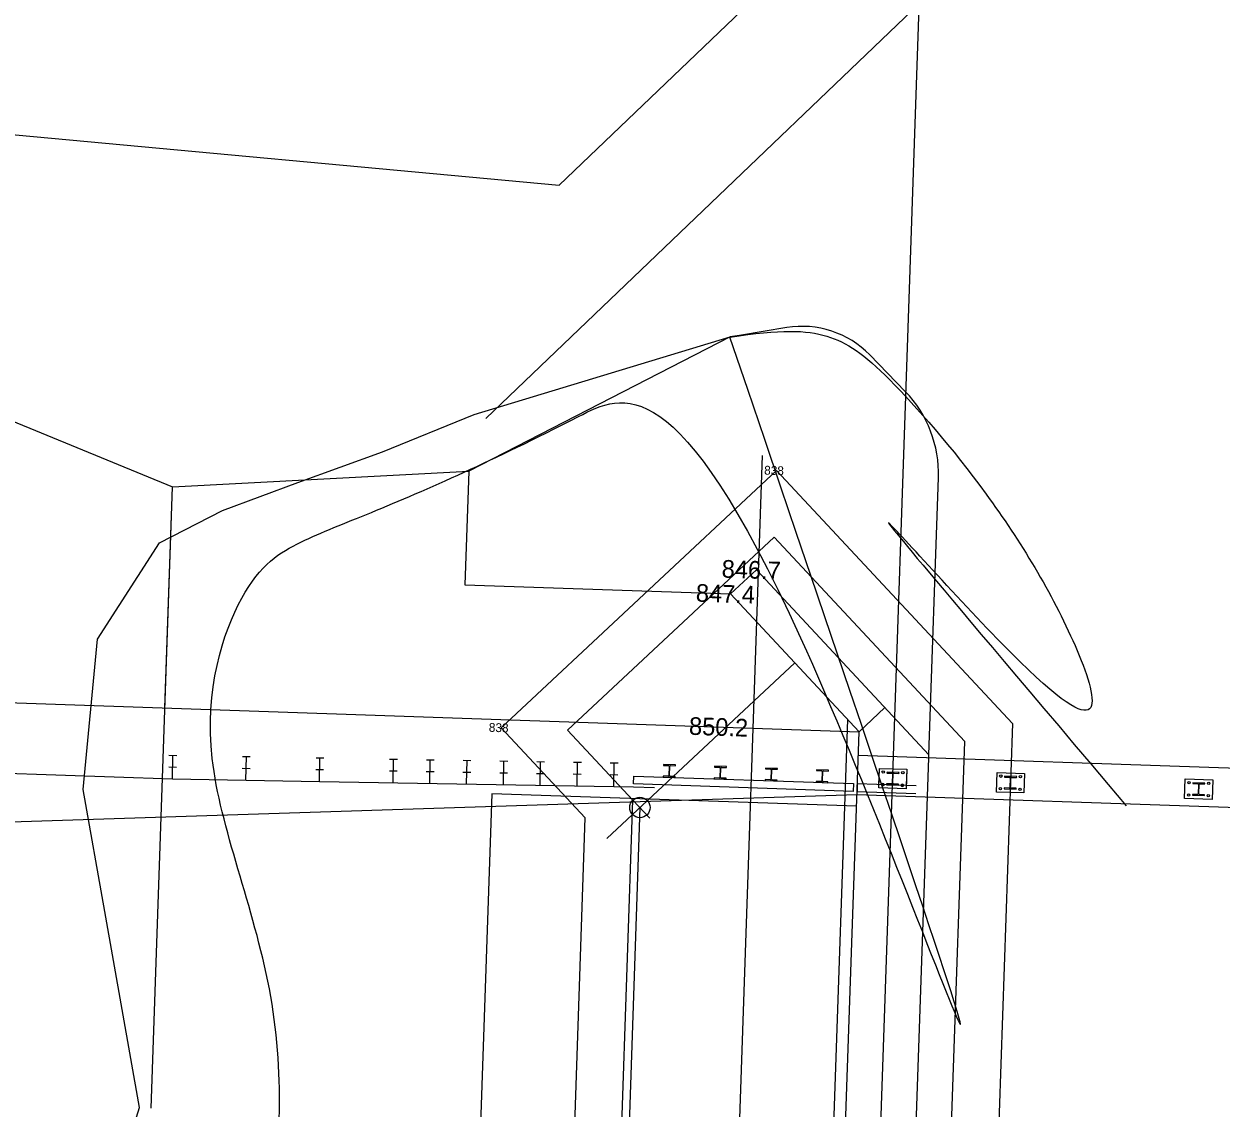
# Model space of a CAD drawing. Extents: x 2191309 to 2193046, y 863659 to 865133.
# Drawn here: x 2192617.6 to 2192668.4, y 863931.1 to 863977.1 of the extents above; entities that cross this region are included whole.
import ezdxf

# ---------------------------------------------------------------- set-up
doc = ezdxf.new("R2010")
doc.units = 0
for name, color, linetype in [('D_Bridge_Abutment', 7, 'Continuous'), ('D_Bridge_Deck', 7, 'Continuous'), ('D_Bridge_Railing', 7, 'Continuous'), ('D_Bridge_Substructure_Hidden', 7, 'Continuous'), ('D_Guardrail_Beam_Lt', 7, 'Continuous'), ('D_Roadway_Edge_Shoulder', 7, 'Continuous'), ('D_Roadway_Edge_TW', 7, 'Continuous'), ('D_Slope_ClearingLimitLine', 7, 'Continuous'), ('D_Slope_Direction', 7, 'Continuous'), ('D_Slope_Toe', 7, 'Continuous'), ('DIMENSIONS', 7, 'Continuous'), ('JUNK', 7, 'Continuous')]:
    doc.layers.add(name, color=color, linetype=linetype)

msp = doc.modelspace()

# ---------------------------------------------------------------- linework, layer by layer
at = {"layer": 'D_Bridge_Abutment'}
for p, q in [((2192649.968, 863964.217), (2192647.951, 863963.884)), ((2192654.997, 863961.503), (2192653.49, 863963.056)), ((2192656.002, 863946.079), (2192656.406, 863957.849)), ((2192647.575, 863952.908), (2192648.671, 863953.932)), ((2192647.575, 863952.908), (2192648.671, 863953.932)), ((2192656.002, 863946.079), (2192648.671, 863953.932)), ((2192648.671, 863953.932), (2192656.002, 863946.079)), ((2192653.034, 863947.06), (2192647.575, 863952.908)), ((2192653.034, 863947.06), (2192654.131, 863948.084)), ((2192651.868, 863913.08), (2192653.034, 863947.06)), ((2192655.998, 863945.958), (2192656.002, 863946.079))]:
    msp.add_line(p, q, dxfattribs=at)
msp.add_lwpolyline([(2192647.951, 863963.884), (2192647.562, 863963.82), (2192636.456, 863958.126), (2192636.29, 863953.295), (2192647.575, 863952.908)], dxfattribs=at)
for centre, radius, start, end in [((2192650.619, 863960.27), 4, 44.1436, 99.3716), ((2192651.409, 863958.021), 5, 358.0343, 44.1436)]:
    msp.add_arc(centre, radius, start, end, dxfattribs=at)
at = {"layer": 'D_Bridge_Deck'}
for p, q in [((2192653, 863946.061), (2192689.978, 863944.792)), ((2192652.943, 863944.395), (2192689.921, 863943.126))]:
    msp.add_line(p, q, dxfattribs=at)
at = {"layer": 'D_Bridge_Railing'}
for p, q in [((2192644.728, 863945.668), (2192644.727, 863945.63)), ((2192644.727, 863945.63), (2192644.937, 863945.622)), ((2192645.234, 863945.65), (2192644.728, 863945.668)), ((2192644.966, 863945.592), (2192644.952, 863945.196)), ((2192644.979, 863945.195), (2192644.992, 863945.591)), ((2192645.023, 863945.62), (2192645.233, 863945.612)), ((2192645.233, 863945.612), (2192645.234, 863945.65)), ((2192646.893, 863945.593), (2192646.892, 863945.555)), ((2192647.4, 863945.576), (2192646.893, 863945.593)), ((2192647.399, 863945.538), (2192647.4, 863945.576)), ((2192644.711, 863945.174), (2192644.71, 863945.136)), ((2192644.71, 863945.136), (2192645.216, 863945.119)), ((2192644.921, 863945.167), (2192644.711, 863945.174)), ((2192645.218, 863945.157), (2192645.007, 863945.164)), ((2192645.216, 863945.119), (2192645.218, 863945.157)), ((2192646.877, 863945.1), (2192646.875, 863945.062)), ((2192646.875, 863945.062), (2192647.382, 863945.045)), ((2192647.087, 863945.093), (2192646.877, 863945.1)), ((2192646.892, 863945.555), (2192647.102, 863945.548)), ((2192647.131, 863945.517), (2192647.117, 863945.121)), ((2192647.144, 863945.12), (2192647.158, 863945.516)), ((2192647.383, 863945.082), (2192647.173, 863945.09)), ((2192647.188, 863945.545), (2192647.399, 863945.538)), ((2192647.382, 863945.045), (2192647.383, 863945.082)), ((2192649.059, 863945.519), (2192649.058, 863945.481)), ((2192649.058, 863945.481), (2192649.268, 863945.474)), ((2192649.565, 863945.502), (2192649.059, 863945.519)), ((2192649.296, 863945.443), (2192649.283, 863945.047)), ((2192649.309, 863945.046), (2192649.323, 863945.442)), ((2192649.354, 863945.471), (2192649.564, 863945.464)), ((2192649.564, 863945.464), (2192649.565, 863945.502)), ((2192651.224, 863945.445), (2192651.223, 863945.407)), ((2192651.223, 863945.407), (2192651.433, 863945.4)), ((2192651.731, 863945.427), (2192651.224, 863945.445)), ((2192651.462, 863945.369), (2192651.448, 863944.973)), ((2192651.475, 863944.972), (2192651.488, 863945.368)), ((2192651.519, 863945.397), (2192651.729, 863945.389)), ((2192651.729, 863945.389), (2192651.731, 863945.427)), ((2192654.221, 863945.341), (2192654.219, 863945.305)), ((2192654.219, 863945.305), (2192654.431, 863945.298)), ((2192654.223, 863945.342), (2192654.221, 863945.304)), ((2192654.731, 863945.324), (2192654.221, 863945.341)), ((2192654.221, 863945.304), (2192654.431, 863945.297)), ((2192654.729, 863945.324), (2192654.223, 863945.342)), ((2192654.46, 863945.266), (2192654.446, 863944.87)), ((2192654.46, 863945.266), (2192654.447, 863944.869)), ((2192654.473, 863944.869), (2192654.487, 863945.265)), ((2192654.473, 863944.869), (2192654.486, 863945.265)), ((2192654.517, 863945.294), (2192654.728, 863945.286)), ((2192654.518, 863945.295), (2192654.729, 863945.287)), ((2192654.728, 863945.286), (2192654.729, 863945.324)), ((2192654.729, 863945.287), (2192654.731, 863945.324)), ((2192659.218, 863945.17), (2192659.216, 863945.133)), ((2192659.216, 863945.133), (2192659.428, 863945.126)), ((2192659.728, 863945.152), (2192659.218, 863945.17)), ((2192659.457, 863945.094), (2192659.444, 863944.698)), ((2192659.47, 863944.697), (2192659.483, 863945.093)), ((2192659.515, 863945.123), (2192659.727, 863945.116)), ((2192659.727, 863945.116), (2192659.728, 863945.152)), ((2192649.042, 863945.026), (2192649.041, 863944.988)), ((2192649.041, 863944.988), (2192649.547, 863944.97)), ((2192649.252, 863945.018), (2192649.042, 863945.026)), ((2192649.548, 863945.008), (2192649.338, 863945.015)), ((2192649.547, 863944.97), (2192649.548, 863945.008)), ((2192651.207, 863944.951), (2192651.206, 863944.913)), ((2192651.206, 863944.913), (2192651.712, 863944.896)), ((2192651.417, 863944.944), (2192651.207, 863944.951)), ((2192651.714, 863944.934), (2192651.504, 863944.941)), ((2192651.712, 863944.896), (2192651.714, 863944.934)), ((2192654.204, 863944.847), (2192654.202, 863944.81)), ((2192654.202, 863944.81), (2192654.713, 863944.793)), ((2192654.206, 863944.848), (2192654.204, 863944.81)), ((2192654.415, 863944.84), (2192654.204, 863944.847)), ((2192654.204, 863944.81), (2192654.711, 863944.793)), ((2192654.416, 863944.841), (2192654.206, 863944.848)), ((2192654.712, 863944.831), (2192654.502, 863944.838)), ((2192654.714, 863944.829), (2192654.503, 863944.837)), ((2192654.711, 863944.793), (2192654.712, 863944.831)), ((2192654.713, 863944.793), (2192654.714, 863944.829)), ((2192659.201, 863944.675), (2192659.199, 863944.639)), ((2192659.199, 863944.639), (2192659.71, 863944.621)), ((2192659.412, 863944.668), (2192659.201, 863944.675)), ((2192659.711, 863944.658), (2192659.5, 863944.665)), ((2192659.71, 863944.621), (2192659.711, 863944.658)), ((2192667.213, 863944.895), (2192667.212, 863944.859)), ((2192667.212, 863944.859), (2192667.423, 863944.852)), ((2192667.723, 863944.878), (2192667.213, 863944.895)), ((2192667.453, 863944.82), (2192667.439, 863944.423)), ((2192667.465, 863944.423), (2192667.479, 863944.819)), ((2192667.511, 863944.849), (2192667.722, 863944.842)), ((2192667.722, 863944.842), (2192667.723, 863944.878)), ((2192667.196, 863944.401), (2192667.195, 863944.365)), ((2192667.195, 863944.365), (2192667.705, 863944.347)), ((2192667.407, 863944.394), (2192667.196, 863944.401)), ((2192667.706, 863944.383), (2192667.495, 863944.391)), ((2192667.705, 863944.347), (2192667.706, 863944.383))]:
    msp.add_line(p, q, dxfattribs=at)
for points in [[(2192643.464, 863945.179), (2192652.792, 863944.859), (2192652.78, 863944.526), (2192643.452, 863944.846), (2192643.464, 863945.179)], [(2192653.874, 863944.822), (2192653.898, 863945.504), (2192655.064, 863945.464), (2192655.04, 863944.782)], [(2192655.463, 863944.767), (2192652.958, 863944.853), (2192652.947, 863944.52), (2192655.451, 863944.434)], [(2192655.04, 863944.782), (2192655.035, 863944.631), (2192653.869, 863944.671), (2192653.874, 863944.822)]]:
    msp.add_lwpolyline(points, dxfattribs=at)
for points in [[(2192653.898, 863945.504), (2192655.064, 863945.464), (2192655.035, 863944.631), (2192653.869, 863944.671)], [(2192658.895, 863945.332), (2192660.061, 863945.292), (2192660.032, 863944.459), (2192658.866, 863944.499)], [(2192666.89, 863945.058), (2192668.056, 863945.018), (2192668.028, 863944.185), (2192666.862, 863944.225)]]:
    msp.add_lwpolyline(points, close=True, dxfattribs=at)
for centre in [(2192654.059, 863945.347), (2192654.059, 863945.347), (2192654.892, 863945.318), (2192654.892, 863945.318), (2192659.056, 863945.175), (2192659.889, 863945.147), (2192654.041, 863944.816), (2192654.874, 863944.787), (2192659.038, 863944.644), (2192659.871, 863944.616), (2192667.052, 863944.901), (2192667.884, 863944.872), (2192667.033, 863944.37), (2192667.866, 863944.341)]:
    msp.add_circle(centre, 0.0521, dxfattribs=at)
for centre, radius, start, end in [((2192644.936, 863945.593), 0.0298, 358.0343, 88.0343), ((2192645.022, 863945.59), 0.0298, 88.0343, 178.0343), ((2192644.922, 863945.197), 0.0298, 268.0343, 358.0343), ((2192645.008, 863945.194), 0.0298, 178.0343, 268.0343), ((2192647.088, 863945.122), 0.0298, 268.0343, 358.0343), ((2192647.101, 863945.518), 0.0298, 358.0343, 88.0343), ((2192647.174, 863945.119), 0.0298, 178.0343, 268.0343), ((2192647.187, 863945.515), 0.0298, 88.0343, 178.0343), ((2192649.267, 863945.444), 0.0298, 358.0343, 88.0343), ((2192649.353, 863945.441), 0.0298, 88.0343, 178.0343), ((2192651.432, 863945.37), 0.0298, 358.0343, 88.0343), ((2192651.518, 863945.367), 0.0298, 88.0343, 178.0343), ((2192654.43, 863945.267), 0.0308, 358.0343, 88.0343), ((2192654.43, 863945.267), 0.0298, 358.0343, 88.0343), ((2192654.517, 863945.264), 0.0308, 88.0343, 178.0343), ((2192654.516, 863945.264), 0.0298, 88.0343, 178.0343), ((2192659.427, 863945.095), 0.0308, 358.0343, 88.0343), ((2192659.514, 863945.092), 0.0308, 88.0343, 178.0343), ((2192649.253, 863945.048), 0.0298, 268.0343, 358.0343), ((2192649.339, 863945.045), 0.0298, 178.0343, 268.0343), ((2192651.418, 863944.974), 0.0298, 268.0343, 358.0343), ((2192651.505, 863944.971), 0.0298, 178.0343, 268.0343), ((2192654.416, 863944.87), 0.0308, 268.0343, 358.0343), ((2192654.417, 863944.871), 0.0298, 268.0343, 358.0343), ((2192654.503, 863944.868), 0.0298, 178.0343, 268.0343), ((2192654.504, 863944.867), 0.0308, 178.0343, 268.0343), ((2192659.413, 863944.699), 0.0308, 268.0343, 358.0343), ((2192659.501, 863944.696), 0.0308, 178.0343, 268.0343), ((2192667.422, 863944.821), 0.0308, 358.0343, 88.0343), ((2192667.51, 863944.818), 0.0308, 88.0343, 178.0343), ((2192667.408, 863944.425), 0.0308, 268.0343, 358.0343), ((2192667.496, 863944.422), 0.0308, 178.0343, 268.0343)]:
    msp.add_arc(centre, radius, start, end, dxfattribs=at)
at = {"layer": 'D_Bridge_Substructure_Hidden'}
for p, q in [((2192640.655, 863947.132), (2192649.426, 863955.321)), ((2192657.523, 863946.649), (2192649.426, 863955.321)), ((2192643.429, 863944.16), (2192640.655, 863947.132)), ((2192651.351, 863912.598), (2192652.552, 863947.577)), ((2192656.374, 863913.183), (2192657.523, 863946.649)), ((2192654.912, 863914.31), (2192655.998, 863945.958)), ((2192642.484, 863916.632), (2192643.429, 863944.16))]:
    msp.add_line(p, q, dxfattribs=at)
msp.add_lwpolyline([(2192652.925, 863943.896), (2192637.435, 863944.427), (2192636.486, 863916.777), (2192651.976, 863916.245)], dxfattribs=at)
at = {"layer": 'D_Guardrail_Beam_Lt'}
for p, q in [((2192623.71, 863945.562), (2192624.043, 863945.557)), ((2192623.718, 863946.062), (2192624.052, 863946.057)), ((2192623.868, 863945.06), (2192623.885, 863946.06)), ((2192626.843, 863946.008), (2192627.176, 863946.003)), ((2192626.992, 863945.006), (2192627.01, 863946.005)), ((2192629.968, 863945.954), (2192630.301, 863945.949)), ((2192630.117, 863944.952), (2192630.134, 863945.951)), ((2192633.092, 863945.9), (2192633.425, 863945.895)), ((2192633.241, 863944.898), (2192633.259, 863945.897)), ((2192634.654, 863945.873), (2192634.988, 863945.868)), ((2192634.804, 863944.871), (2192634.821, 863945.87)), ((2192636.217, 863945.846), (2192636.55, 863945.841)), ((2192636.366, 863944.844), (2192636.383, 863945.843)), ((2192637.779, 863945.819), (2192638.112, 863945.814)), ((2192637.928, 863944.817), (2192637.945, 863945.816)), ((2192639.341, 863945.792), (2192639.674, 863945.787)), ((2192639.49, 863944.79), (2192639.508, 863945.789)), ((2192640.903, 863945.765), (2192641.237, 863945.76)), ((2192641.053, 863944.763), (2192641.07, 863945.762)), ((2192642.466, 863945.738), (2192642.799, 863945.733)), ((2192642.615, 863944.736), (2192642.632, 863945.735)), ((2192614.498, 863945.381), (2192623.868, 863945.06)), ((2192623.868, 863945.06), (2192630.117, 863944.952)), ((2192626.834, 863945.508), (2192627.168, 863945.503)), ((2192629.959, 863945.454), (2192630.292, 863945.449)), ((2192633.083, 863945.4), (2192633.417, 863945.395)), ((2192634.646, 863945.373), (2192634.979, 863945.368)), ((2192636.208, 863945.346), (2192636.541, 863945.341)), ((2192637.77, 863945.319), (2192638.103, 863945.314)), ((2192639.332, 863945.292), (2192639.666, 863945.287)), ((2192640.895, 863945.265), (2192641.228, 863945.26)), ((2192642.457, 863945.238), (2192642.79, 863945.233)), ((2192630.117, 863944.952), (2192642.615, 863944.736)), ((2192642.615, 863944.736), (2192643.448, 863944.721)), ((2192643.448, 863944.721), (2192644.344, 863944.69))]:
    msp.add_line(p, q, dxfattribs=at)
for centre, start, end in [((2192654.041, 863944.816), 358.0343, 178.0343), ((2192654.041, 863944.816), 178.0343, 358.0343), ((2192654.874, 863944.787), 358.0343, 178.0343), ((2192654.874, 863944.787), 178.0343, 358.0343)]:
    msp.add_arc(centre, 0.0521, start, end, dxfattribs=at)
at = {"layer": 'D_Roadway_Edge_Shoulder'}
msp.add_line((2192614.601, 863948.379), (2192653.034, 863947.06), dxfattribs=at)
at = {"layer": 'D_Roadway_Edge_TW'}
msp.add_lwpolyline([(2192473.456, 863947.873), (2192498.419, 863946.364), (2192602.969, 863942.775), (2192652.943, 863944.395)], dxfattribs=at)
at = {"layer": 'D_Slope_ClearingLimitLine'}
msp.add_line((2192588.181, 863975.083), (2192640.301, 863970.263), dxfattribs=at)
msp.add_lwpolyline([(2192640.301, 863970.263), (2192661.289, 863990.353), (2192705.075, 863988.85), (2192726.461, 863965.527)], dxfattribs=at)
at = {"layer": 'D_Slope_Direction'}
msp.add_line((2192623.551, 863948.072), (2192623.873, 863957.452), dxfattribs=at)
at = {"layer": 'D_Slope_Toe'}
msp.add_lwpolyline([(2192574.285, 863970.289), (2192578.069, 863970.997), (2192599.068, 863963.566), (2192615.733, 863960.799), (2192623.873, 863957.452), (2192636.456, 863958.126)], dxfattribs=at)
at = {"layer": 'DIMENSIONS'}
msp.add_line((2192653.157, 863906.91), (2192656.738, 864011.242), dxfattribs=at)
at = {"layer": 'JUNK'}
for p, q in [((2192647.954, 863930.225), (2192648.934, 863958.793)), ((2192622.968, 863931.082), (2192623.873, 863957.452)), ((2192650.304, 863949.984), (2192642.313, 863942.523)), ((2192641.402, 863943.401), (2192637.828, 863947.229)), ((2192643.429, 863944.16), (2192644.149, 863943.389)), ((2192643.726, 863943.842), (2192643.264, 863930.386)), ((2192640.514, 863917.529), (2192641.402, 863943.401))]:
    msp.add_line(p, q, dxfattribs=at)
for points in [[(2192637.185, 863960.359), (2192663.224, 863985.284), (2192702.807, 863983.925), (2192712.853, 863972.969)], [(2192622.469, 863931.099), (2192620.992, 863939.432), (2192620.081, 863944.605), (2192620.684, 863950.986), (2192623.313, 863955.075), (2192626.001, 863956.454), (2192629.191, 863957.634), (2192632.79, 863958.942), (2192636.685, 863960.527), (2192647.562, 863963.82)], [(2192637.828, 863947.229), (2192649.523, 863958.147), (2192659.55, 863947.408), (2192658.344, 863912.287), (2192647.605, 863902.26), (2192636.686, 863913.955)], [(2192636.839, 863896.208), (2192634.583, 863900.089), (2192630.873, 863902.598), (2192626.884, 863904.672), (2192623.432, 863906.932), (2192620.816, 863909.439), (2192618.716, 863912.913), (2192618.547, 863918.11), (2192619.713, 863922.238), (2192622.469, 863931.099)]]:
    msp.add_lwpolyline(points, dxfattribs=at)
msp.add_circle((2192643.726, 863943.842), 0.433, dxfattribs=at)
for points in [[(2192647.549, 863963.813), (2192649.708, 863964.151), (2192651.852, 863964.078), (2192653.916, 863962.626), (2192658.522, 863957.374), (2192662.584, 863950.752), (2192664.38, 863943.914), (2192647.549, 863963.813), (2192664.38, 863943.914)], [(2192664.087, 863915.13), (2192661.833, 863908.973), (2192659.632, 863905.174), (2192657.321, 863902.93), (2192654.418, 863900.048), (2192652.473, 863897.638), (2192650.675, 863895.417), (2192648.365, 863894.638), (2192644.671, 863895.34), (2192641.195, 863897.953), (2192634.581, 863903.022), (2192630.83, 863904.841), (2192627.384, 863906.997), (2192624.834, 863909.746), (2192623.07, 863913.243), (2192624.488, 863919.117), (2192628.399, 863925.562), (2192628.765, 863936.224), (2192624.451, 863946.4), (2192626.793, 863953.699), (2192629.251, 863955.168), (2192632.124, 863956.268), (2192636.17, 863957.994), (2192640.744, 863960.211), (2192647.549, 863963.813), (2192664.087, 863915.13), (2192647.549, 863963.813)]]:
    msp.add_open_spline(points, degree=3, dxfattribs=at)

# ---------------------------------------------------------------- texts
for s, height, p in [('838', 0.375, (2192648.997, 863957.978)), ('846.7', 0.75, (2192647.188, 863953.607)), ('847.4', 0.75, (2192646.091, 863952.584)), ('850.2', 0.75, (2192645.8, 863946.933)), ('838', 0.375, (2192637.302, 863947.059))]:
    msp.add_text(s, height=height, rotation=358.0343, dxfattribs=at).set_placement(p)

doc.saveas('drawing.dxf')
